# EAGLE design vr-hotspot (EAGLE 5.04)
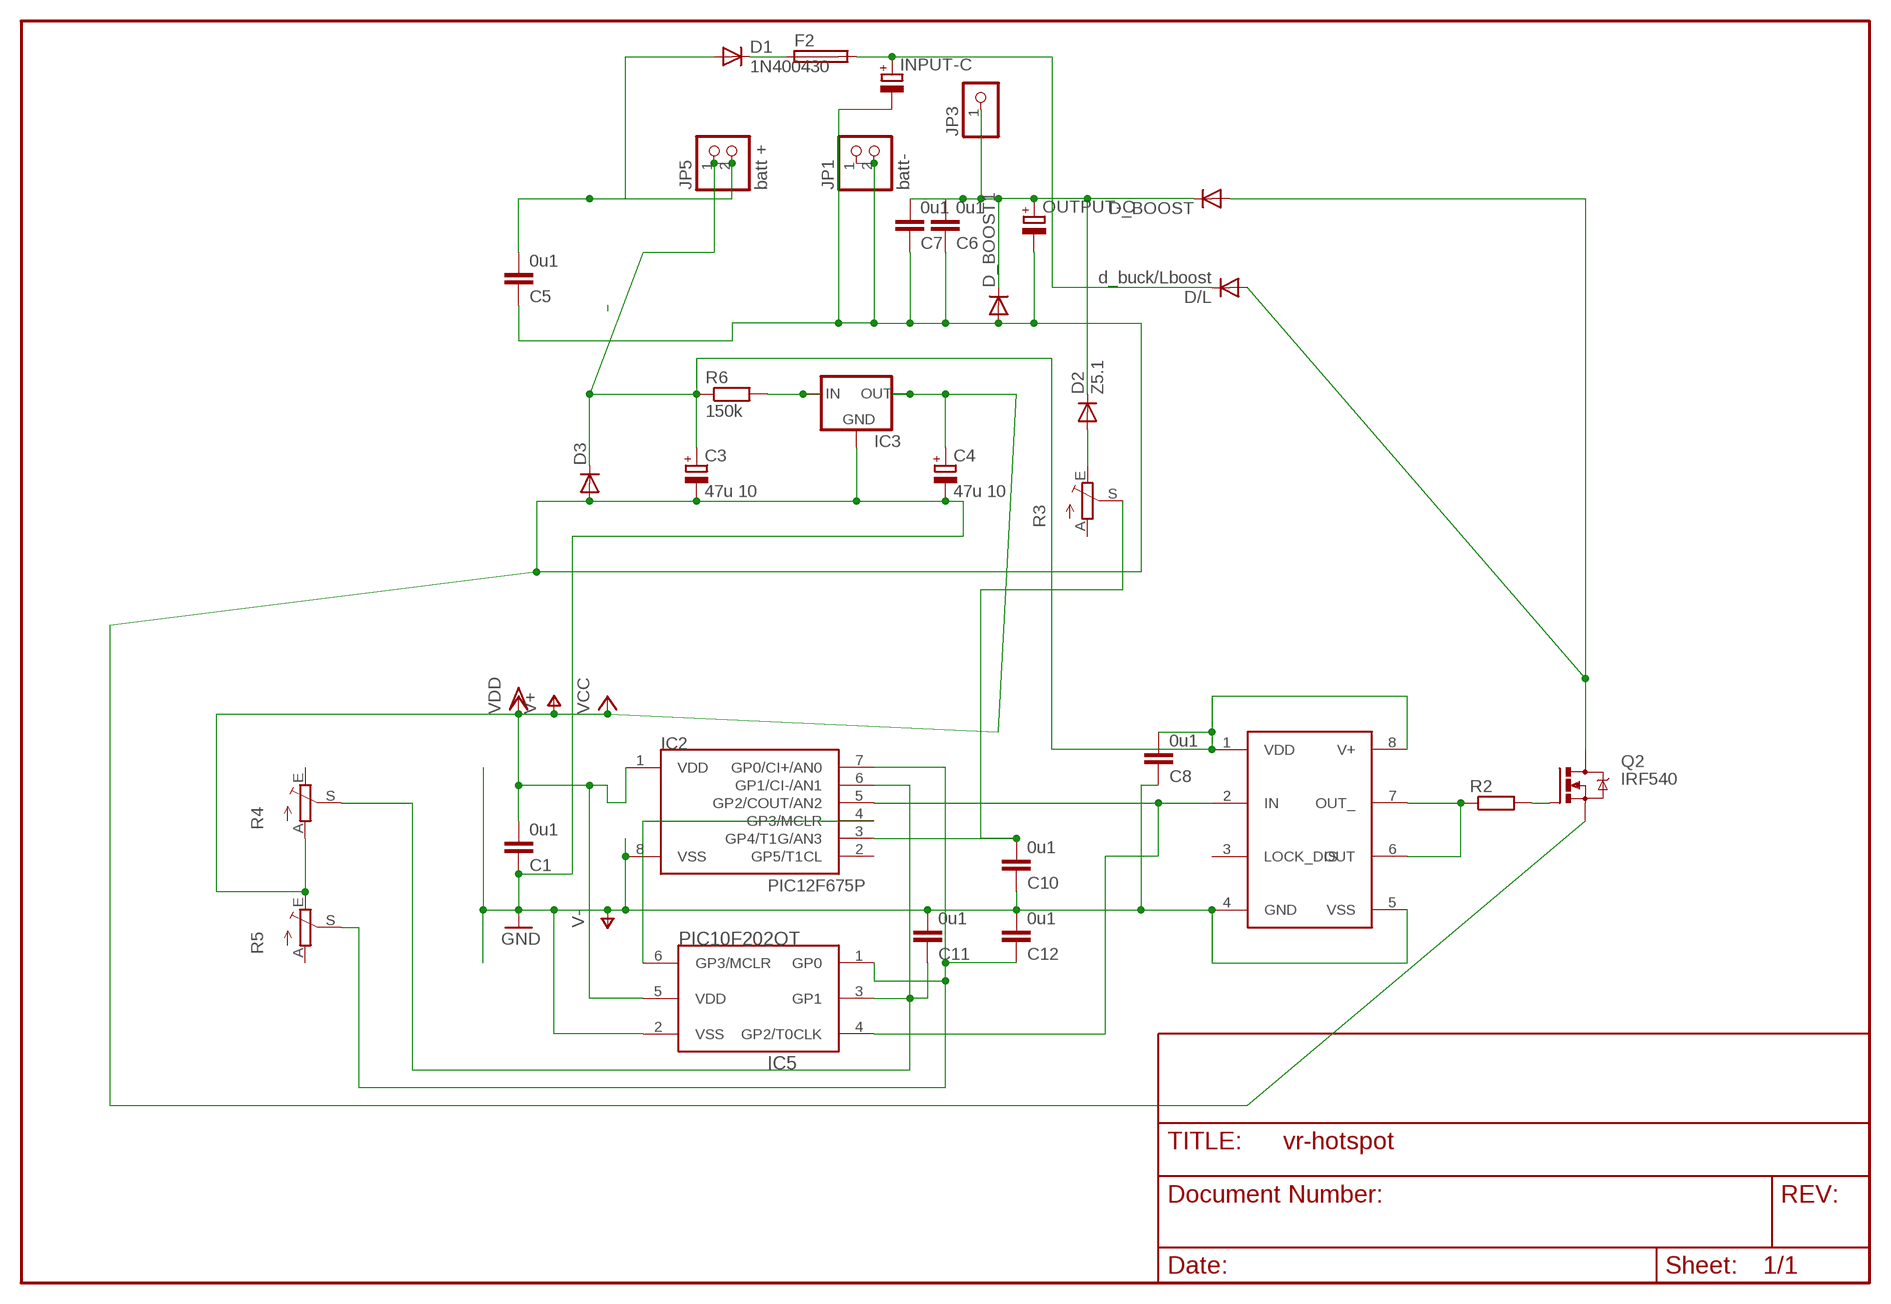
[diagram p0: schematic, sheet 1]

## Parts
C1  0u1  C-EUC1206  [C1206]
C3  47u 10  CPOL-EUE2,5-6E  [E2,5-6E]
C4  47u 10  CPOL-EUE2.5-6  [E2,5-6]
C5  0u1  C-EUC1206  [C1206]
C6  0u1  C-EUC1206  [C1206]
C7  0u1  C-EUC1206  [C1206]
C8  0u1  C-EUC1206  [C1206]
C10  0u1  C-EUC1206  [C1206]
C11  0u1  C-EUC1206  [C1206]
C12  0u1  C-EUC1206  [C1206]
D1  1N400430  [DO41-30]
D2  Z5.1  DIODE-C1702-05  [C1702-05]
D3  DIODE-DO201-30  [DO201-30]
D/L  d_buck/Lboost  DIODE-C1702-15  [C1702-15]
D_BOOST  DIODE-SOD61C  [SOD61C]
D_BOOST1  DIODE-DO201-15  [DO201-15]
F2  SH22  [SH22]
IC1  TC4432X  [SO-08]
IC2  PIC12F675P  [DIL8]
IC3  78LXX  [78LXX]
IC5  PIC10F202OT  [SOT23-6]
INPUT-C  CPOL-EUE7.5-18  [E7,5-18]
JP1  batt-  PINHD-1X2  [1X02]
JP3  PINHD-1X1  [1X01]
JP5  batt +  PINHD-1X2  [1X02]
OUTPUT-C  CPOL-EUE7.5-18  [E7,5-18]
Q2  IRF540  [TO220BV]
R2  R-EU_R1206  [R1206]
R3  TRIM_EU-CA6V  [CA6V]
R4  TRIM_EU-CA6V  [CA6V]
R5  TRIM_EU-CA6V  [CA6V]
R6  150k  R-EU_0204/7  [0204/7]

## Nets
LOAD: C6.2 C7.2 D2.C D_BOOST1.C D_BOOST.C JP3.1 OUTPUT-C.+
N$1: C3.+ C5.2 C8.2 D1.A D3.C IC1.1(VDD) IC1.8(V+) JP5.1 JP5.2 R6.1
N$2: D/L.C F2.2 INPUT-C.+
N$3: D1.C F2.1
N$7: IC1.6(OUT) IC1.7(OUT_) R2.1
N$9: D/L.A D_BOOST.A Q2.D
N$10: IC2.4(GP3/MCLR) IC5.6(GP3/MCLR)
N$12: C10.2 IC2.3(GP4/T1G/AN3) R3.S
N$13: C12.1 IC2.7(GP0/CI+/AN0) IC5.1(GP0) R5.S
N$14: IC1.2(IN) IC2.5(GP2/COUT/AN2) IC5.4(GP2/T0CLK)
N$15: C11.1 IC2.6(GP1/CI-/AN1) IC5.3(GP1) R4.S
N$16: D2.A R3.E
N$17: Q2.G R2.2
N$20: IC3.IN R6.2
V+: C1.2 C4.+ IC2.1(VDD) IC3.OUT IC5.5(VDD) R4.A R5.E ; supply symbol labelled VCC, VDD
V-: C1.1 C3.- C4.- C5.1 C6.1 C7.1 C8.1 C10.1 C11.2 C12.2 D3.A D_BOOST1.A IC1.4(GND) IC1.5(VSS) IC2.8(VSS) IC3.GND IC5.2(VSS) INPUT-C.- JP1.1 JP1.2 OUTPUT-C.- Q2.S ; supply symbol labelled GND
Unconnected: IC1.3(LOCK_DIS) IC2.2(GP5/T1CL) R3.A R4.E R5.A

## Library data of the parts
C1 C5-C8 C10-C12 = rcl:C-EU: CAPACITOR, European symbol
C3 C4 INPUT-C OUTPUT-C = rcl:CPOL-EU: POLARIZED CAPACITOR, European symbol
D1 = diode-1:1N4004: DIODE
D2 D3 D/L D_BOOST D_BOOST1 = diode:DIODE-: DIODE
F2 = fuse:SH22: FUSE HOLDER
IC1 = microchip:TC4432
IC2 = microchip-3:PIC12F6*: uPC nW 1k Program Flash memory 2x Timer Comparator 10b A/D converter/ 4xIN
IC3 = v-reg:78LXX: VOLTAGE REGULATOR
IC5 = microchip-5:PIC10F20*: uPC nW 0,25/0,5k Program Flash memory
JP1 JP5 = pinhead:PINHD-1X2: PIN HEADER
JP3 = pinhead:PINHD-1X1: PIN HEADER
Q2 = transistor-power:IRF540: HEXFET Power MOSFET
R2 = rcl-2:R-EU_: RESISTOR, European symbol
R3-R5 = pot:TRIM_EU-: POTENTIOMETER
R6 = rcl:R-EU_: RESISTOR, European symbol

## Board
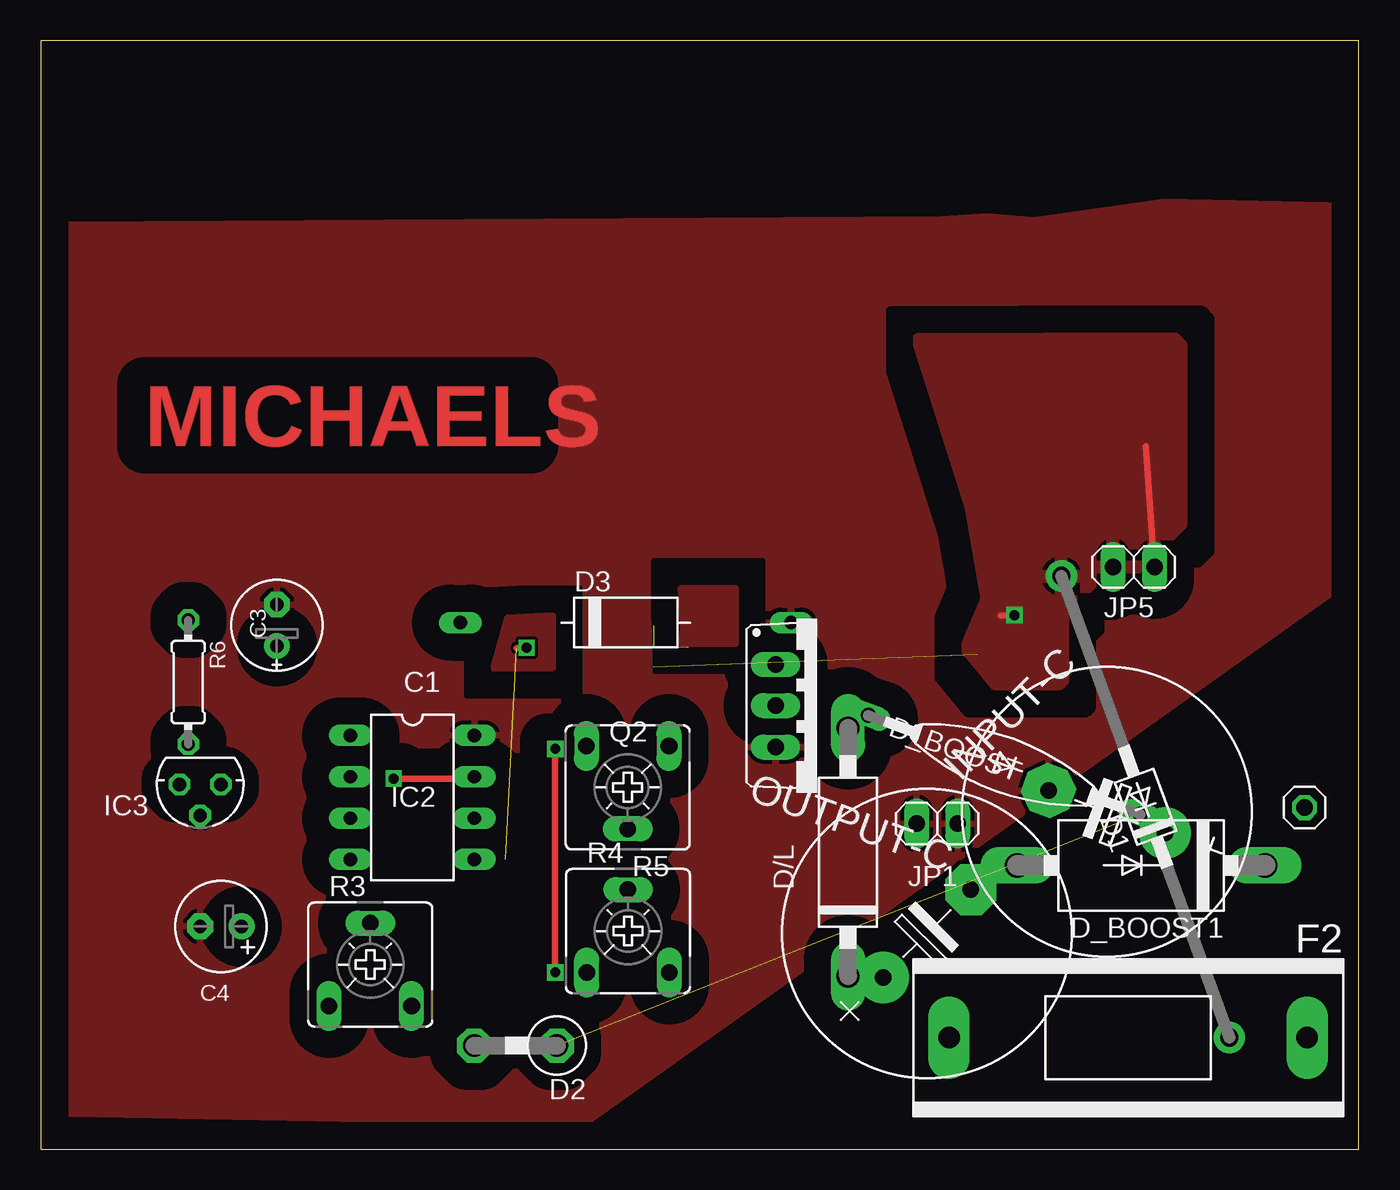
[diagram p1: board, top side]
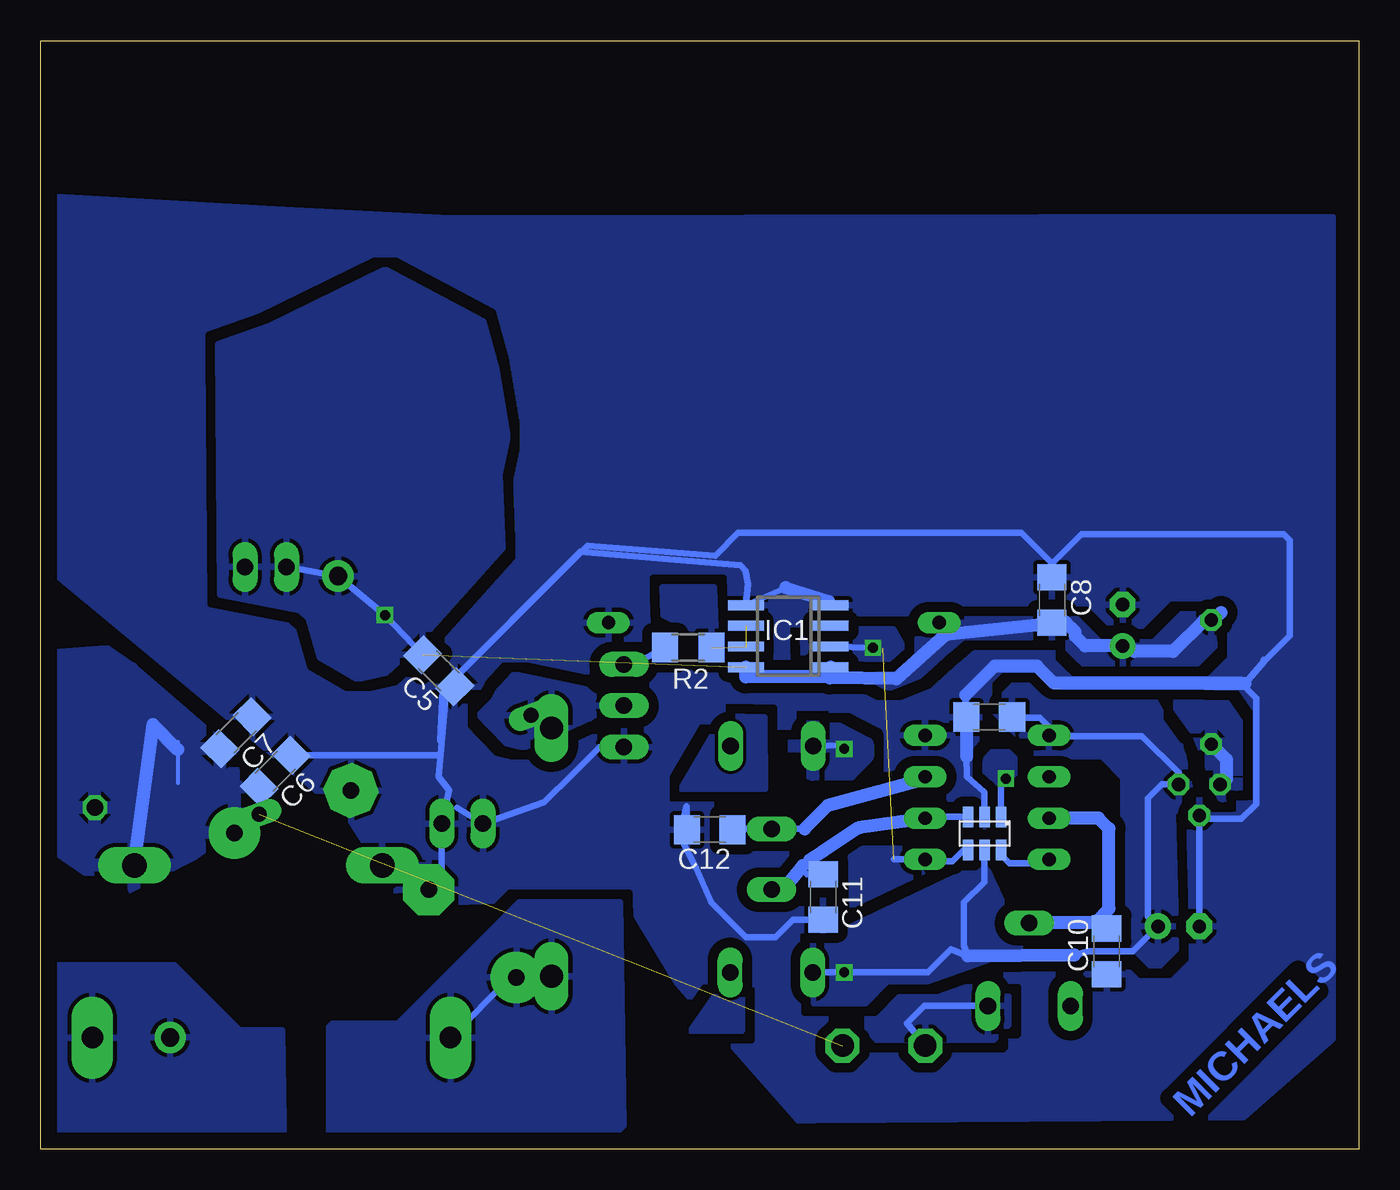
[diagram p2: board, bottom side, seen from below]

Size 81 x 68.09 mm. Coordinates in mm from the lower left corner, seen from the top.
Outline: 0,0 81,0 81,68.09 0,68.09 0,0
Copper layers (1*16): Top 0.035mm / dielectric 1.5mm / Bottom 0.035mm
Design rules "default": minimum track width 10mil, minimum drill 24mil, track to track 8mil, track to pad 8mil, pad to pad 8mil, via to via 8mil, smd to smd 8mil, copper to edge 40mil, drill to drill 8mil, minimum pad ring 10mil, minimum via ring 8mil, stop-mask expansion 4mil, vias tented up to drill 0mil, thermal gap 10mil

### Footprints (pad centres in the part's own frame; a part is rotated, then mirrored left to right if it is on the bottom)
C1206 = smd 1.6 x 1.8: 1 -1.4,0; 2 1.4,0
E2,5-6E = drill 0.813 pad 1.575 round: + -1.27,0 | drill 0.813 pad 1.575 octagon: - 1.27,0
E2,5-6 = drill 0.813 pad 1.6 round: + -1.27,0 | drill 0.813 pad 1.6 octagon: - 1.27,0
DO41-30 = drill 1.118 pad 1.93 round: A 15.08,0; C -15.08,0
C1702-05 = drill 1.397 octagon: A 2.54,0; C -2.54,0
DO201-30 = drill 0.813 long: A 10.16,0; C -10.16,0
C1702-15 = drill 1.397 long: A 7.62,0; C -7.62,0
SOD61C = drill 0.914 long: A 8.89,0; C -8.89,0
DO201-15 = drill 1.499 long: A 7.62,0; C -7.62,0
SH22 = drill 1.321 pad 2.54 long: 1 -10.998,0; 2 10.998,0
SO-08 = smd 0.6 x 2.2: 1 -1.905,-2.6; 2 -0.635,-2.6; 3 0.635,-2.6; 4 1.905,-2.6; 5 1.905,2.6; 6 0.635,2.6; 7 -0.635,2.6; 8 -1.905,2.6
DIL8 = drill 0.813 long: 1 -3.81,-3.81; 2 -1.27,-3.81; 3 1.27,-3.81; 4 3.81,-3.81; 5 3.81,3.81; 6 1.27,3.81; 7 -1.27,3.81; 8 -3.81,3.81
78LXX = drill 0.813 octagon: GND 0,1.905; IN 1.27,0; OUT -1.27,0
SOT23-6 = smd 0.635 x 1.27: 1 -1.016,-1.016; 2 0,-1.016; 3 1.016,-1.016; 4 1.016,1.016; 5 0,1.016; 6 -1.016,1.016
E7,5-18 = drill 1.016 pad 3.15 round: + -3.81,0 | drill 1.016 pad 3.15 octagon: - 3.81,0
1X02 = drill 1.016 long: 1 -1.27,0; 2 1.27,0
1X01 = drill 1.016 octagon: 1 0,0
TO220BV = drill 1.016 long: D 0,-2.54; G -2.54,-2.54; S 2.54,-2.54
R1206 = smd 1.6 x 1.803: 1 -1.422,0; 2 1.422,0
CA6V = drill 1.016 long: A -2.54,-2.54; E 2.54,-2.54; S 0,2.54
0204/7 = drill 0.813 octagon: 1 -3.81,0; 2 3.81,0

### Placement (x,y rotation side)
C1  22.7,26.54 0 bottom
C3  14.51,32.18 90 top
C4  11.07,13.68 180 top
C5  56.54,29.38 135 bottom
C6  66.59,23.21 225 bottom
C7  68.99,25.58 225 bottom
C8  18.86,33.73 270 bottom
C10  15.49,12.15 90 bottom
C11  32.92,15.49 270 bottom
C12  39.88,19.62 180 bottom
D1  67.88,21.03 110 top
D2  29.18,6.36 180 top
D3  35.95,32.35 0 top
D/L  49.61,18.24 90 top
D_BOOST  59.22,23.61 160 top
D_BOOST1  67.62,17.42 180 top
F2  66.82,6.85 180 top
IC1  35.06,31.51 90 bottom
IC2  22.84,21.6 270 top
IC3  9.8,22.4 180 top
IC5  23,19.39 180 bottom
INPUT-C  54.46,13.24 45 top
JP1  55.09,20 180 top
JP3  77.67,20.98 0 top
JP5  67.17,35.76 180 top
OUTPUT-C  65.51,20.73 160 top
Q2  47.7,27.24 270 top
R2  41.21,30.81 180 bottom
R3  20.25,11.34 0 top
R4  36.09,13.4 0 top
R5  36.07,22.22 180 top
R6  9.06,28.69 270 top

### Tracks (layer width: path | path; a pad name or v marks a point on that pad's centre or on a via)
LOAD  (1 unrouted)
  Bottom 0.254: 72.58,22.48 72.58,24.55 72.58,25.02
  Bottom 0.406: OUTPUT-C.+ 68.71,19.42 D_BOOST.C 67.57,22.21 C6.2
  Bottom 0.813: D_BOOST1.C 74.1,26.07 72.58,24.55
  pour Bottom (isolate 0.61, rank 2): 68.51,20.29 71.64,18.12 75.74,16.03 76.62,16.07 81.04,19.1 81.04,30.26 76.98,30.59 75.4,29.51 69.44,24.38
N$1  (via drill 0.6)  (1 unrouted)
  Top 0.406: JP5.1 67.92,43.18 | v59.84,32.8 59,32.77
  Bottom 0.406: C5.2 v59.84,32.8 D1.A JP5.2
  Bottom 0.813: IC1.8 37.66,29 37.13,29.02 32.62,29.02 IC1.1 32.46,29.02 32.51,28.96 28.42,28.89 25.41,31.59 18.02,32.37 17.42,31.77 17.42,31.51 16.82,30.91 C3.+ 14.13,30.91 13.8,30.58 11.43,30.58 9.51,32.5 R6.1 8.99,32.44 8.47,32.96
  pour Bottom (isolate 0.61, rank 2): 52.31,43.76 52.81,41.45 52.61,36.91 58.18,30.71 59.79,29.27 61.54,28.85 63.83,30.19 64.51,32.54 65.07,33.1 69.97,34.06 70.1,49.43 67.07,50.53 59.83,54.04 53.81,50.86 52.99,47.83
  pour Top (isolate 0.61): 69.62,49.81 70.08,49.35 70.08,38.39 66.76,35.08 64.83,35.08 62.79,33.03 62.79,28.79 62.56,28.56 58.68,28.56 56.88,30.77 58.19,33.82 57.21,39.29 53.91,49.75
  pour Bottom (isolate 0.61, rank 2): 9.15,32.87 10.89,32.87 12.63,31.13 15.88,31.13 17.31,32.55 25.5,32.59 26.62,31.81 27.68,30.87 29.96,28.82 28.89,28.32 26.97,29.07 25.64,30.28 25.26,30.63 24.34,31.45 18.17,31.45 17.85,31.13 17.85,30.72 16.35,29.22 10.5,29.22 8.84,30.89
N$2
  Bottom 0.406: D/L.C 51.7,10.62 INPUT-C.+ 52.12,10.55 F2.2
  pour Bottom (isolate 0.61): 45.41,15.16 51.61,15.16 59.08,7.7 63.1,7.7 63.27,7.53 63.27,-0.23 62.72,-0.77 47.39,-0.77 45.18,1.44
N$3
  pour Bottom (isolate 0.61, rank 2): 66.16,7.3 68.78,7.3 72.78,11.3 80.36,11.3 81.05,10.62 81.05,0.56 79.66,-0.83 66.43,-0.83 66.02,-0.42
N$4
  pour Top: 39.49,31.93 39.35,34.47 42.68,34.47 42.68,31.05 39.42,31.05
N$5
  pour Top: 28.69,32.65 27.82,29.53 31.44,29.53 31.44,32.8
N$6
  pour Bottom: 37.87,11.84 37.91,7.26 41.06,7.26
N$7  (2 unrouted)
  pour Bottom (isolate 0.61): 40.32,30.59 39.53,32.03 39.63,34.53 42.78,34.53 42.73,32.79 40.27,31.61
N$8
  pour Bottom: 39.04,26.59 36.52,26.52 36.48,22.11 41.64,22.15
N$9
  pour Bottom (isolate 1.27): 46.03,27.95 51.91,29.17 54.15,26.73 52.4,24.94 51.25,24.66 47.24,26.48 46.39,26.9
N$10
  Bottom 0.406: IC5.6 21.98,18.1 21.46,17.58 19.25,17.58 IC2.4
N$12
  Bottom 0.406: 20.63,13.91 20.61,13.88 R3.S | C10.2 15.71,13.55 16.14,13.98
  Bottom 0.813: IC2.3 16,20.33 15.35,19.68 15.35,14.77 16.14,13.98 16.21,13.91 20.63,13.91
N$13  (via drill 0.6)
  Top 0.406: v21.69,22.76 26.54,22.76 IC2.7
  Bottom 0.406: IC5.1 21.98,22.47 v21.69,22.76 | 34.06,19.68 R5.S 38.42,19.68 C12.1 | 26.46,22.78 26.72,22.81 IC2.7
  Bottom 0.813: 34.06,19.68 32.65,21.09 26.46,22.78
  pour Bottom (isolate 0.61): 21.17,23.04 21.17,24.04 21.5,24.37 22.55,24.37 22.96,23.96 22.96,22.95 22.35,22.34
N$14  (via drill 0.6)  (1 unrouted)
  Top 0.406: v29.85,30.8 29.25,30.78
  Bottom 0.406: IC5.4 24.27,18.38 24.96,17.68 26.54,17.68 IC2.5 28.56,17.79 | v29.85,30.8 IC1.2
  pour Bottom (isolate 0.61, rank 2): 27.72,18.44 30.45,18.44 31.2,18.2 31.09,13.47 30.04,14.19 28.69,14.19 26.51,16.36
  pour Bottom (isolate 0.61): 30.5,29.44 29.03,29.83 28.28,29.53 28.06,30.98 28.6,31.94 34.19,31.95 34.08,29.95 30.81,29.76
N$15
  Bottom 0.406: 35.65,15.84 35.28,16.09 R4.S | 34.17,17.44 33.73,17.77 33.55,17.77 33.54,17.75 34.16,17.13 | 32.96,18.27 32.91,18.23 | 25.89,20.26 27.22,20.26 27.23,20.25 | IC5.3 26.58,20.41 IC2.6 | 34.16,17.13 35.02,16.27 35.73,16.27 36.12,15.89 | C11.1 33.92,16.89 34.16,17.13
  Bottom 0.813: IC2.6 27.23,20.25 30.74,19.74 32.96,18.27 33.73,17.77 | 34.17,17.44 35.28,16.09
N$16
  Bottom 0.406: D2.A 27.77,7.72 26.69,8.8 R3.E
  pour Bottom (isolate 0.61, rank 2): 23.15,9.94 28.36,9.94 30.21,8.09 30.21,7.3 29.64,6.73 22.42,6.73 21.55,7.61 21.55,9.39 21.87,9.7
N$17
  Bottom 0.406: Q2.G 45.09,29.78 44.9,29.59 R2.2
N$20
  Bottom 0.813: R6.2 9.06,24.87 8.12,23.93 8.12,22.75 8.53,22.34 IC3.IN
  pour Bottom (isolate 0.61): 9.89,25.59 11.9,28.33 9.06,28.42 7.1,25.58 7.1,22.02 7.41,21.7 8.37,21.7
V+  (via drill 0.6)
  Top 0.406: v31.62,10.86 v31.62,24.59
  Bottom 0.406: C1.2 21.27,26.5 19.61,26.5 19.03,25.93 IC2.1 18.98,25.36 13.32,25.36 11.07,23.11 IC3.OUT 12.11,22.4 12.95,21.57 12.95,14.29 C4.+ 13.88,12.14 16.66,12.14 17.46,11.91 | v31.62,10.86 26.49,10.86 25.08,12.27 24.02,11.85 24.25,12.5 24.25,15.15 23,16.41 IC5.5 | v31.62,10.86 R4.A v31.62,10.86 | R5.E 31.79,24.8 v31.62,24.59
  Bottom 0.813: 17.46,11.91 24.02,11.85
  pour Bottom (isolate 0.61): 34.72,25.93 32.22,25.93 30.2,24.92 30.2,24.08 31.25,23.03 33.59,23.03 34.69,23.33
  pour Bottom (isolate 0.61, rank 3): 11.24,13.77 11.24,12.24 12.19,11.29 12.85,11.29 14.46,12.9 14.46,22.8 15.8,24.13 19.68,24.13 22.64,27.09 22.63,27.09 19.97,29.74 17.51,29.74 13.74,29.02 12.47,27.43 10.89,24.68 10.28,21.76 11.43,20.61
  pour Bottom (isolate 0.61): 23,17.58 33.94,12.36 33.94,12.12 33.47,12.12 33.47,8.95 30.3,8.95 28.95,10.3 26.5,10.3 20.62,12.4
V-
  Bottom 0.406: IC1.4 35.21,34.49 IC1.5 37.52,34.73 37.68,35.53 38.01,35.87 47.85,36.69 56.31,28.23 56.45,25.09 | 56.42,24.2 C6.1 | 55.42,20.97 JP1.2 50.06,21.3 48.26,23.09 46.64,24.7 Q2.S | C11.2 34.76,14.09 35.85,13.01 37.66,13.01 39.79,15.13 40.74,17.29 41.75,19.27 41.31,21.06 C12.2 | IC5.2 23,21.89 23.05,21.95 24.08,22.87 24.1,24.13 | 5.83,29.93 4.24,31.52 4.24,37.39 4.61,37.76 17.05,37.76 18.86,35.95 C8.1 18.86,35.98 20.74,37.86 38.15,37.86 39.54,36.46 47.38,37.06 56.04,28.4 56.55,22.89 55.91,22.05 JP1.1 56.36,16.74 INPUT-C.- | 5.83,29.93 5.83,30.05 | 6.98,28.61 5.83,29.93 | 24.16,27.89 24.16,26.6 C1.1 | 7.24,28.63 6.31,27.7 6.31,21.2 7.22,20.28 9.59,20.28 IC3.GND C4.-
  Bottom 0.813: 35.21,34.49 32.57,33.64 | 9.51,28.63 6.98,28.61 | 9.51,28.63 18.73,28.63 19.77,29.67 22.39,29.67 24.16,27.89 | 7.24,28.63 9.51,28.63 | C1.1 24.1,24.13
  pour Bottom (isolate 0.61, rank 4): 1.6,57.29 1.6,6.79 7.11,1.97 33.44,1.78 34.45,1.78 41.87,10.15 44.13,13.92 45.09,15.56 58.67,15.05 62.14,20.46 80.77,35.9 80.77,44.59 81.1,58.56 66.62,57.75 55.83,57.18
  pour Top (isolate 1.676, rank 3): 1.46,56.78 55.48,57.12 58.14,57.32 61.11,57.07 69.08,58.19 80.49,57.96 80.79,35.19 33.49,1.6 1.79,2.17

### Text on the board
Top: MICHAELS
Bottom: MICHAELS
